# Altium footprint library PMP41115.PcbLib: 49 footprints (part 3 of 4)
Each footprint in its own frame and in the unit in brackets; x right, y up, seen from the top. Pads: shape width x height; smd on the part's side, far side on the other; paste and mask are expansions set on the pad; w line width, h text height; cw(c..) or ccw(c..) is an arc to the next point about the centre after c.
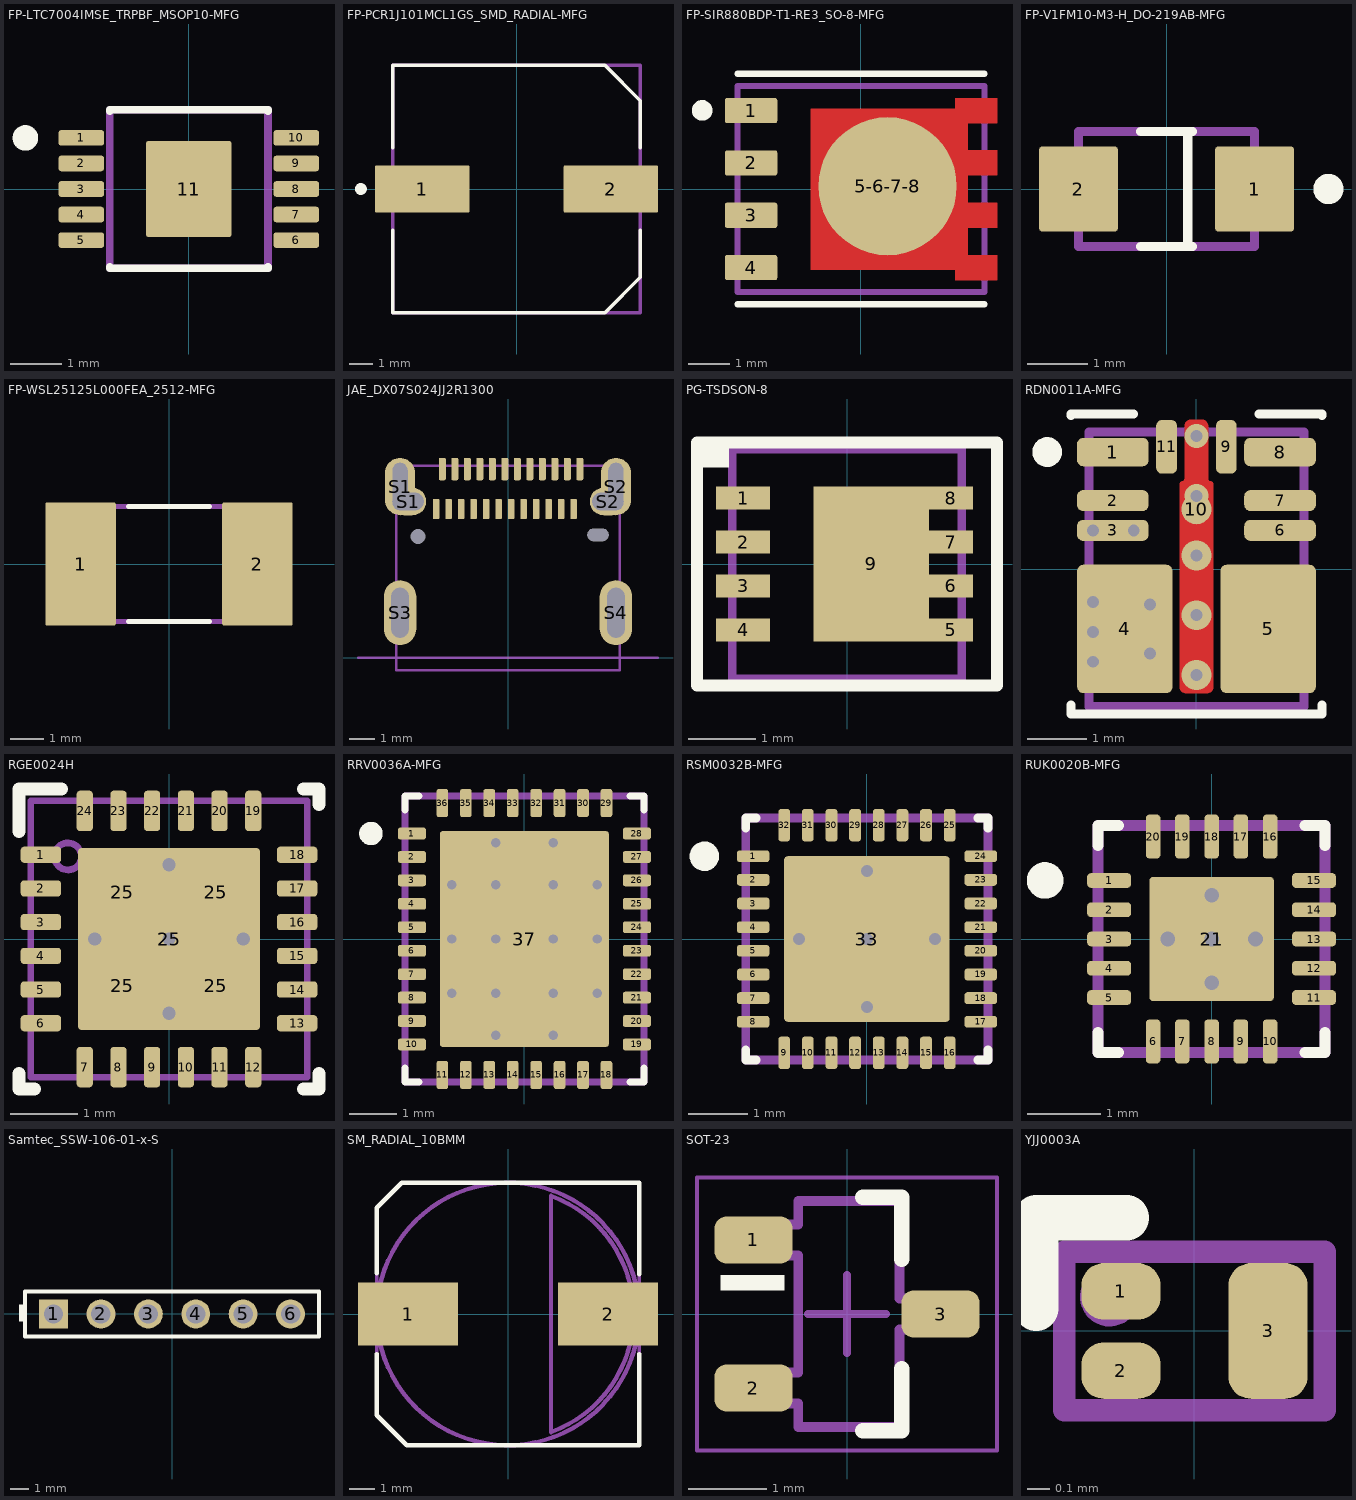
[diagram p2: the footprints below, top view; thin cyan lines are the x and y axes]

## FP-LTC7004IMSE_TRPBF_MSOP10-MFG [mm]
height 4.8
pads (11):
  rrect33% 0.889x0.305 smd paste+0 mask+0: 1(-2.105,1) 2(-2.105,0.5) 3(-2.105,0) 4(-2.105,-0.5) 5(-2.105,-1) 6(2.105,-1) 7(2.105,-0.5) 8(2.105,0) 9(2.105,0.5) 10(2.105,1)
  rrect6% 1.68x1.88 smd paste+0 mask+0: 11(0,0)
Top Overlay:
  circle w0.25: c-3.2,1 r0.125
  lines w0.15: -1.551,-1.528 -1.551,-1.551 1.551,-1.551 1.551,-1.528 ; -1.551,1.528 -1.551,1.551 1.551,1.551 1.551,1.528
Mechanical 5:
  lines w0.15: -1.551,-1.551 1.551,-1.551 1.551,1.551 -1.551,1.551 -1.551,-1.551
  text ".Designator" at 0,0 h0.5
3D body "IC_LTC7004IMSE_TRPBF_MSOP10.STEP": height 0.25, standoff 0, extent -2.65,-1.803 2.65,1.803

## FP-PCR1J101MCL1GS_SMD_RADIAL-MFG [mm]
height 4.8
pads (2):
  rrect5% 4x2 smd paste+0 mask+0: 1(-4,0) 2(4,0)
Top Overlay:
  circle w0.25: c-6.6,0 r0.125
  lines w0.15: -5.25,-1.75 -5.25,-5.25 3.75,-5.25 5.25,-3.75 5.25,-1.75 ; -5.25,1.75 -5.25,5.25 3.75,5.25 5.25,3.75 5.25,1.75
Mechanical 5:
  lines w0.15: -5.25,-5.25 5.25,-5.25 5.25,5.25 -5.25,5.25 -5.25,-5.25
  text ".Designator" at 0,0 h0.5
3D body "Cap_PCR1J101MCL1GS_SMD_RADIAL.STEP": height 0.25, standoff 0, extent -6.25,-5.5 6.25,5.5

## FP-SIR880BDP-T1-RE3_SO-8-MFG [mil]
height 188.98
pads (5):
  rrect16% 50x24 smd paste+0 mask+0: 1(-105,75) 2(-105,25) 3(-105,-25) 4(-105,-75)
  round 132.13 smd paste+0 mask+0: 5-6-7-8(25.41,2.72)
Top Layer:
  region: -48,77 90,77 90,87 130,87 130,63 102,63 102,37 130,37 130,13 102,13 102,-13 130,-13 130,-37 102,-37 102,-63 130,-63 130,-87 90,-87 90,-77 -48,-77
Top Overlay:
  circle w9.84: c-151.77,75.19 r4.92
  lines w5.91: -117.91,-110.04 117.91,-110.04 ; -117.91,110.24 117.91,110.24
Mechanical 5:
  lines w5.91: -117.91,-98.43 117.91,-98.43 117.91,98.43 -117.91,98.43 -117.91,-98.43
  text ".Designator" at 1.97,8.53 h19.68
3D body "Trans_SIR880BDP-T1-RE3_SO-8.STEP": height 46.07, standoff 0, extent -120.41,-102.22 121.72,100.53

## FP-V1FM10-M3-H_DO-219AB-MFG [mm]
height 1.1
pads (2):
  rrect8% 1.3x1.4 smd paste+0 mask+0: 1(1.45,0) 2(-1.45,0)
Top Overlay:
  circle w0.25: c2.667,0 r0.125
  lines w0.15: -0.425,-0.95 0.425,-0.95 ; -0.425,0.95 0.425,0.95 ; 0.35,-0.87 0.35,0.87
Mechanical 5:
  lines w0.15: -1.45,-0.95 -1.45,0.95 1.45,0.95 1.45,-0.95 -1.45,-0.95
  text ".Designator" at 0,0 h0.5
3D body "Diode_V1FM10-M3-H_DO-219AB.STEP": height 1.08, standoff 0, extent -1.85,-0.9 1.85,0.9

## FP-WSL25125L000FEA_2512-MFG [mm]
height 4.8
pads (2):
  rrect5% 2.11x3.68 smd paste+0 mask+0: 1(-2.645,0) 2(2.645,0)
Top Overlay:
  lines w0.15: -1.215,-1.717 1.215,-1.717 ; -1.215,1.717 1.215,1.717
Mechanical 5:
  lines w0.15: -3.302,-1.717 -3.302,1.717 3.302,1.717 3.302,-1.717 -3.302,-1.717
  text ".Designator" at 0.05,0.217 h0.5
3D body "Res_WSL25125L000FEA_2512.STEP": height 0.25, standoff 0, extent -3.8,-1.94 3.8,1.94

## JAE_DX07S024JJ2R1300 [mm] "Receptacle, USB 3.1 Type C, R/A, SMT"
height 3.29
pads (32):
  rrect37% 0.27x0.9 smd: A1(-2.625,7.55) A2(-2.125,7.55) A3(-1.625,7.55) A4(-1.125,7.55) A5(-0.625,7.55) A6(-0.125,7.55) A7(0.375,7.55) A8(0.875,7.55) A9(1.375,7.55) A10(1.875,7.55) A11(2.375,7.55) A12(2.875,7.55)
  round 0.3 hole 0.6 unplated mask+0.102: ALIGN1(-3.6,4.85)
  rrect100% 0.55x0.3 hole 0.5 slot 0.85 at 0 deg unplated mask+0.102: ALIGN2(3.6,4.915)
  rrect37% 0.27x0.8 smd: B1(2.625,5.95) B2(2.125,5.95) B3(1.625,5.95) B4(1.125,5.95) B5(0.625,5.95) B6(0.125,5.95) B7(-0.375,5.95) B8(-0.875,5.95) B9(-1.375,5.95) B10(-1.875,5.95) B11(-2.375,5.95) B12(-2.875,5.95)
  rrect100% 1.2x2.3 hole 0.6 slot 1.9 at 90 deg: S1(-4.32,6.85) S2(4.32,6.85)
  rrect100% 1.45x1.1 hole 0.7 slot 1.25 at 0 deg: S1(-3.995,6.25) S2(3.995,6.25)
  rrect100% 1.3x2.6 hole 0.7 slot 2 at 90 deg: S3(-4.32,1.8) S4(4.32,1.8)
Mechanical 1:
  lines w0.1: -6,0 6,0
Mechanical 5:
  lines w0.1: -4.47,-0.5 -4.47,7.67 -3.47,7.67 3.47,7.67 4.47,7.67 4.47,-0.5 3.47,-0.5 -3.47,-0.5 -4.47,-0.5
  text ".Designator" at -1.8,4.336 h1.02
3D body "DX07S024JJ2R1300.stp": height 3.14, standoff -0.6, extent -4.47,-0.5 4.47,7.67

## PG-TSDSON-8 [mm] "Infineon recommended land pattern"
height 1.1
pads (9):
  rect 0.8x0.34 smd: 1(-1.538,0.975) 2(-1.538,0.325) 3(-1.538,-0.325) 4(-1.538,-0.975)
  rect 0.65x0.34 smd: 5(1.538,-0.975) 6(1.538,-0.325) 7(1.538,0.325) 8(1.538,0.975)
  rect 1.71x2.29 smd: 9(0.358,0)
Top Overlay:
  rectangle: -2.212,1.425 -1.75,1.76
  lines w0.178: -2.22,-1.8 0.1,-1.8 2.22,-1.8 2.22,0 2.22,1.8 0.1,1.8 -2.22,1.8 -2.22,0 -2.22,-1.8
Mechanical 5:
  lines w0.127: -1.7,-1.7 -1.7,1.7 1.7,1.7 1.7,-1.7 -1.7,-1.7
  text ".Designator" at -1.538,-0.325 h0.76
3D body "PG-TSDSON-8.stp": height 1.1, standoff 0, extent -1.7,-1.7 1.7,1.7

## RDN0011A-MFG [mm]
pads (11):
  rrect42% 1.2x0.475 smd paste-1000 mask-1000: 1(-1.4,1.962) 8(1.4,1.962)
  rrect57% 1.2x0.35 smd paste-1000 mask-1000: 2(-1.4,1.15) 3(-1.4,0.65) 6(1.4,0.65) 7(1.4,1.15)
  rrect13% 1.6x2.15 smd paste-1000 mask-1000: 4(-1.2,-1) 5(1.2,-1)
  rrect57% 0.35x0.9 smd paste-1000 mask-1000: 9(0.5,2.05) 11(-0.5,2.05)
  round 0.504 smd paste-1000 mask-1000: 10(0,1.005)
via 0,-1.77 diameter 0.5 hole 0.2
via 0,-0.77 diameter 0.5 hole 0.2
via 0,0.23 diameter 0.5 hole 0.2
via 0,1.23 diameter 0.4 hole 0.2
via 0,2.23 diameter 0.4 hole 0.2
via -1.73,-0.55 diameter 0.5 hole 0.2
via -1.73,-1.05 diameter 0.5 hole 0.2
via -1.73,-1.55 diameter 0.5 hole 0.2
via -0.78,-0.59 diameter 0.5 hole 0.2
via -0.78,-1.41 diameter 0.5 hole 0.2
via -1.73,0.65 diameter 0.35 hole 0.2
via -1.05,0.65 diameter 0.35 hole 0.2
Top Layer:
  region: -0.2,2.4 -0.2,2.42 -0.185,2.457 -0.157,2.485 -0.12,2.5 -0.1,2.5 0.1,2.5 0.12,2.5 0.157,2.485 0.185,2.457 0.2,2.42 0.2,2.4 0.2,1.515 0.201,1.507 0.207,1.493 0.218,1.482 0.232,1.476 0.24,1.475 0.248,1.475 0.263,1.469 0.274,1.458 0.28,1.443 0.28,1.435 0.28,-1.975 0.28,-1.995 0.265,-2.032 0.237,-2.06 0.2,-2.075 0.18,-2.075 -0.18,-2.075 -0.2,-2.075 -0.237,-2.06 -0.265,-2.032 -0.28,-1.995 -0.28,-1.975 -0.28,1.435 -0.28,1.443 -0.274,1.458 -0.263,1.469 -0.248,1.475 -0.24,1.475 -0.232,1.476 -0.218,1.482 -0.207,1.493 -0.201,1.507 -0.2,1.515
Top Overlay:
  circle w0.25: c-2.5,1.962 r0.125
  lines w0.15: -2.1,-2.275 -2.1,-2.425 2.1,-2.425 2.1,-2.275 ; -2.1,2.575 -2.1,2.6 -1.05,2.6 ; 1.05,2.6 2.1,2.6 2.1,2.575
Top Paste:
  drawing of 23 lines, arcs and shapes, not listed
Top Solder:
  drawing of 11 lines, arcs and shapes, not listed
Mechanical 5:
  lines w0.15: -1.8,-2.3 -1.8,2.3 1.8,2.3 1.8,-2.3 -1.8,-2.3
  text ".Designator" at 0.05,0.317 h0.5
3D body "IC_TPSM365R6RDNR_QFN-FCMOD11.STEP": height 2.1, standoff 0, extent -1.75,-2.25 1.75,2.25

## RGE0024H [mm] "QFN, 24-Leads, Body 4x4mm, Pitch 0.5mm, Thermal Pad 2.7x2.7mm, TI Recommended"
height 1
pads (29):
  rrect42% 0.6x0.24 smd: 1(-1.9,1.25) 2(-1.9,0.75) 3(-1.9,0.25) 4(-1.9,-0.25) 5(-1.9,-0.75) 6(-1.9,-1.25) 13(1.9,-1.25) 14(1.9,-0.75) 15(1.9,-0.25) 16(1.9,0.25) 17(1.9,0.75) 18(1.9,1.25)
  rrect42% 0.24x0.6 smd: 7(-1.25,-1.9) 8(-0.75,-1.9) 9(-0.25,-1.9) 10(0.25,-1.9) 11(0.75,-1.9) 12(1.25,-1.9) 19(1.25,1.9) 20(0.75,1.9) 21(0.25,1.9) 22(-0.25,1.9) 23(-0.75,1.9) 24(-1.25,1.9)
  rrect50% 1.19x1.19 on Top Paste: 25(-0.695,-0.695) 25(-0.695,0.695) 25(0.695,-0.695) 25(0.695,0.695)
  rrect4% 2.7x2.7 smd paste-1.35: 25(0,0)
via 0,-1.1 diameter 0.5 hole 0.2
via 1.1,0 diameter 0.5 hole 0.2
via 0,0 diameter 0.5 hole 0.2
via -1.1,0 diameter 0.5 hole 0.2
via 0,1.1 diameter 0.5 hole 0.2
Top Overlay:
  lines w0.2: -2.225,-2 -2.225,-2.225 -2,-2.225 ; -2.225,1.6 -2.225,2.225 -1.6,2.225 ; 2,-2.225 2.225,-2.225 2.225,-2 ; 2,2.225 2.225,2.225 2.225,2
Mechanical 5:
  circle w0.1: c-1.5,1.225 r0.2
  lines w0.1: -2.05,-2.05 -2.05,2.05 2.05,2.05 2.05,-2.05 -2.05,-2.05
  text ".Designator" at -1.9,-0.7 h1.8
3D body: height 1, standoff 0, extent -2.075,-2.075 2.075,2.075
3D body: height 1.01, standoff 0.5, extent -1.699,1.026 -1.301,1.424

## RRV0036A-MFG [mm]
height 4.8
pads (37):
  rrect40% 0.6x0.25 smd paste+0 mask+0: 1(-2.4,2.25) 2(-2.4,1.75) 3(-2.4,1.25) 4(-2.4,0.75) 5(-2.4,0.25) 6(-2.4,-0.25) 7(-2.4,-0.75) 8(-2.4,-1.25) 9(-2.4,-1.75) 10(-2.4,-2.25) 19(2.4,-2.25) 20(2.4,-1.75) 21(2.4,-1.25) 22(2.4,-0.75) 23(2.4,-0.25) 24(2.4,0.25) 25(2.4,0.75) 26(2.4,1.25) 27(2.4,1.75) 28(2.4,2.25)
  rrect40% 0.25x0.6 smd paste+0 mask+0: 11(-1.75,-2.9) 12(-1.25,-2.9) 13(-0.75,-2.9) 14(-0.25,-2.9) 15(0.25,-2.9) 16(0.75,-2.9) 17(1.25,-2.9) 18(1.75,-2.9) 29(1.75,2.9) 30(1.25,2.9) 31(0.75,2.9) 32(0.25,2.9) 33(-0.25,2.9) 34(-0.75,2.9) 35(-1.25,2.9) 36(-1.75,2.9)
  rrect3% 3.6x4.6 smd paste-1000 mask+0: 37(0,0)
via 0.615,-2.05 diameter 0.5 hole 0.2
via -0.615,-2.05 diameter 0.5 hole 0.2
via 0.615,2.05 diameter 0.5 hole 0.2
via -0.615,2.05 diameter 0.5 hole 0.2
via 0.615,0 diameter 0.5 hole 0.2
via -0.615,0 diameter 0.5 hole 0.2
via 0.615,-1.16 diameter 0.5 hole 0.2
via -0.615,-1.16 diameter 0.5 hole 0.2
via 0.615,1.16 diameter 0.5 hole 0.2
via -0.615,1.16 diameter 0.5 hole 0.2
via 1.55,1.16 diameter 0.5 hole 0.2
via -1.55,1.16 diameter 0.5 hole 0.2
via 1.55,-1.16 diameter 0.5 hole 0.2
via -1.55,-1.16 diameter 0.5 hole 0.2
via 1.55,0 diameter 0.5 hole 0.2
via -1.55,0 diameter 0.5 hole 0.2
Top Overlay:
  circle w0.25: c-3.275,2.25 r0.125
  lines w0.15: -2.55,-2.75 -2.55,-3.05 -2.25,-3.05 ; -2.55,2.75 -2.55,3.05 -2.25,3.05 ; 2.25,-3.05 2.55,-3.05 2.55,-2.75 ; 2.25,3.05 2.55,3.05 2.55,2.75
Top Paste:
  drawing of 12 lines, arcs and shapes, not listed
Mechanical 5:
  lines w0.15: -2.55,-3.05 -2.55,3.05 2.55,3.05 2.55,-3.05 -2.55,-3.05
  text ".Designator" at 0.05,0.217 h0.5
3D body "IC_BQ25751RRVT_VQFN36.STEP": height 0.25, standoff 0, extent -2.8,-3.3 2.8,3.3

## RSM0032B-MFG [mm]
height 4.8
pads (33):
  rrect50% 0.55x0.2 smd paste+0 mask+0: 1(-1.925,1.4) 2(-1.925,1) 3(-1.925,0.6) 4(-1.925,0.2) 5(-1.925,-0.2) 6(-1.925,-0.6) 7(-1.925,-1) 8(-1.925,-1.4) 17(1.925,-1.4) 18(1.925,-1) 19(1.925,-0.6) 20(1.925,-0.2) 21(1.925,0.2) 22(1.925,0.6) 23(1.925,1) 24(1.925,1.4)
  rrect50% 0.2x0.55 smd paste+0 mask+0: 9(-1.4,-1.925) 10(-1,-1.925) 11(-0.6,-1.925) 12(-0.2,-1.925) 13(0.2,-1.925) 14(0.6,-1.925) 15(1,-1.925) 16(1.4,-1.925) 25(1.4,1.925) 26(1,1.925) 27(0.6,1.925) 28(0.2,1.925) 29(-0.2,1.925) 30(-0.6,1.925) 31(-1,1.925) 32(-1.4,1.925)
  rrect4% 2.8x2.8 smd paste-1000 mask+0: 33(0,0)
via 0,-1.15 diameter 0.5 hole 0.2
via 0,1.15 diameter 0.5 hole 0.2
via 1.15,0 diameter 0.5 hole 0.2
via 0,0 diameter 0.5 hole 0.2
via -1.15,0 diameter 0.5 hole 0.2
Top Overlay:
  circle w0.25: c-2.75,1.4 r0.125
  lines w0.15: -2.05,-1.875 -2.05,-2.05 -1.875,-2.05 ; -2.05,1.875 -2.05,2.05 -1.875,2.05 ; 1.875,-2.05 2.05,-2.05 2.05,-1.875 ; 1.875,2.05 2.05,2.05 2.05,1.875
Top Paste:
  region: 1.33,-0.15 1.33,-1.28 1.33,-1.29 1.322,-1.308 1.308,-1.322 1.29,-1.33 1.28,-1.33 0.15,-1.33 0.14,-1.33 0.122,-1.322 0.108,-1.308 0.1,-1.29 0.1,-1.28 0.1,-0.15 0.1,-0.14 0.108,-0.122 0.122,-0.108 0.14,-0.1 0.15,-0.1 1.28,-0.1 1.29,-0.1 1.308,-0.108 1.322,-0.122 1.33,-0.14
  region: -1.28,-1.33 -1.29,-1.33 -1.308,-1.322 -1.322,-1.308 -1.33,-1.29 -1.33,-1.28 -1.33,-0.15 -1.33,-0.14 -1.322,-0.122 -1.308,-0.108 -1.29,-0.1 -1.28,-0.1 -0.15,-0.1 -0.14,-0.1 -0.122,-0.108 -0.108,-0.122 -0.1,-0.14 -0.1,-0.15 -0.1,-1.28 -0.1,-1.29 -0.108,-1.308 -0.122,-1.322 -0.14,-1.33 -0.15,-1.33
  region: 0.1,0.15 0.1,1.28 0.1,1.29 0.108,1.308 0.122,1.322 0.14,1.33 0.15,1.33 1.28,1.33 1.29,1.33 1.308,1.322 1.322,1.308 1.33,1.29 1.33,1.28 1.33,0.15 1.33,0.14 1.322,0.122 1.308,0.108 1.29,0.1 1.28,0.1 0.15,0.1 0.14,0.1 0.122,0.108 0.108,0.122 0.1,0.14
  region: -0.1,0.15 -0.1,0.14 -0.108,0.122 -0.122,0.108 -0.14,0.1 -0.15,0.1 -1.28,0.1 -1.29,0.1 -1.308,0.108 -1.322,0.122 -1.33,0.14 -1.33,0.15 -1.33,1.28 -1.33,1.29 -1.322,1.308 -1.308,1.322 -1.29,1.33 -1.28,1.33 -0.15,1.33 -0.14,1.33 -0.122,1.322 -0.108,1.308 -0.1,1.29 -0.1,1.28
Mechanical 5:
  lines w0.15: -2.05,-2.05 -2.05,2.05 2.05,2.05 2.05,-2.05 -2.05,-2.05
  text ".Designator" at 0.05,0.217 h0.5
3D body "IC_TPS26750RSMR_VQFN32.STEP": height 0.25, standoff 0, extent -2.3,-2.3 2.3,2.3

## RUK0020B-MFG [mm]
height 4.8
pads (21):
  rrect50% 0.6x0.2 smd paste+0 mask+0: 1(-1.4,0.8) 2(-1.4,0.4) 3(-1.4,0) 4(-1.4,-0.4) 5(-1.4,-0.8) 11(1.4,-0.8) 12(1.4,-0.4) 13(1.4,0) 14(1.4,0.4) 15(1.4,0.8)
  rrect50% 0.2x0.6 smd paste+0 mask+0: 6(-0.8,-1.4) 7(-0.4,-1.4) 8(0,-1.4) 9(0.4,-1.4) 10(0.8,-1.4) 16(0.8,1.4) 17(0.4,1.4) 18(0,1.4) 19(-0.4,1.4) 20(-0.8,1.4)
  rrect6% 1.7x1.7 smd paste-1000 mask+0: 21(0,0)
via 0,0.6 diameter 0.5 hole 0.2
via 0,-0.6 diameter 0.5 hole 0.2
via 0.6,0 diameter 0.5 hole 0.2
via 0,0 diameter 0.5 hole 0.2
via -0.6,0 diameter 0.5 hole 0.2
Top Overlay:
  circle w0.25: c-2.275,0.8 r0.125
  lines w0.15: -1.55,-1.275 -1.55,-1.55 -1.275,-1.55 ; -1.55,1.275 -1.55,1.55 -1.275,1.55 ; 1.275,-1.55 1.55,-1.55 1.55,-1.275 ; 1.275,1.55 1.55,1.55 1.55,1.275
Top Paste:
  region: 0.095,-0.145 0.095,-0.135 0.103,-0.117 0.117,-0.103 0.135,-0.095 0.145,-0.095 0.795,-0.095 0.805,-0.095 0.823,-0.103 0.837,-0.117 0.845,-0.135 0.845,-0.145 0.845,-0.795 0.845,-0.805 0.837,-0.823 0.823,-0.837 0.805,-0.845 0.795,-0.845 0.145,-0.845 0.135,-0.845 0.117,-0.837 0.103,-0.823 0.095,-0.805 0.095,-0.795
  region: -0.795,-0.845 -0.805,-0.845 -0.823,-0.837 -0.837,-0.823 -0.845,-0.805 -0.845,-0.795 -0.845,-0.145 -0.845,-0.135 -0.837,-0.117 -0.823,-0.103 -0.805,-0.095 -0.795,-0.095 -0.145,-0.095 -0.135,-0.095 -0.117,-0.103 -0.103,-0.117 -0.095,-0.135 -0.095,-0.145 -0.095,-0.795 -0.095,-0.805 -0.103,-0.823 -0.117,-0.837 -0.135,-0.845 -0.145,-0.845
  region: 0.095,0.795 0.095,0.805 0.103,0.823 0.117,0.837 0.135,0.845 0.145,0.845 0.795,0.845 0.805,0.845 0.823,0.837 0.837,0.823 0.845,0.805 0.845,0.795 0.845,0.145 0.845,0.135 0.837,0.117 0.823,0.103 0.805,0.095 0.795,0.095 0.145,0.095 0.135,0.095 0.117,0.103 0.103,0.117 0.095,0.135 0.095,0.145
  region: -0.145,0.845 -0.135,0.845 -0.117,0.837 -0.103,0.823 -0.095,0.805 -0.095,0.795 -0.095,0.145 -0.095,0.135 -0.103,0.117 -0.117,0.103 -0.135,0.095 -0.145,0.095 -0.795,0.095 -0.805,0.095 -0.823,0.103 -0.837,0.117 -0.845,0.135 -0.845,0.145 -0.845,0.795 -0.845,0.805 -0.837,0.823 -0.823,0.837 -0.805,0.845 -0.795,0.845
Mechanical 5:
  lines w0.15: -1.55,-1.55 -1.55,1.55 1.55,1.55 1.55,-1.55 -1.55,-1.55
  text ".Designator" at 0,0 h0.5
3D body "IC_TPD4S480RUKR_WQFN20.STEP": height 0.25, standoff 0, extent -1.8,-1.8 1.8,1.8

## Samtec_SSW-106-01-x-S [mm] "Receptacle, 6x1, 2.54mm, TH"
height 8.64
pads (6):
  rect 1.55x1.55 hole 1.04: 1(-6.35,0)
  round 1.55 hole 1.04: 2(-3.81,0) 3(-1.27,0) 4(1.27,0) 5(3.81,0) 6(6.35,0)
Top Overlay:
  rectangle: -8.2,-0.4 -7.9,0.5
  lines w0.2: -7.874,-1.207 7.874,-1.207 7.874,1.206 -7.874,1.206 -7.874,-1.207
Mechanical 5:
  lines w0.1: -7.874,-1.207 -7.874,1.206 7.874,1.206 7.874,-1.207 -7.874,-1.207
  text ".Designator" at -1.524,-0.508 h1.02
3D body "SSW-106-01-T-S.stp": height 8.51, standoff -2.64, extent -7.874,-1.207 7.874,1.207

## SM_RADIAL_10BMM [mm] "Nichicon 10x10"
height 10.5
pads (2):
  rect 4x2.5 smd: 1(-4,0) 2(4,0)
Top Overlay:
  lines w0.178: -5.25,-1.6 -5.25,-4.046 -4.046,-5.25 5.25,-5.25 5.25,-1.6 ; -5.25,1.624 -5.25,4.25 -4.25,5.25 5.25,5.25 5.25,1.597
Mechanical 5:
  lines w0.127: -5.25,-4.046 -5.25,4.25 -4.25,5.25 5.25,5.25 5.25,-5.25 -4.046,-5.25 -5.25,-4.046
  text ".Designator" at -1.524,-0.508 h1.02
Mechanical 13:
  circle w0.178: c0,0 r5.25
  lines w0.178: 1.72,-4.725 ccw(c0,0) 1.72,4.725 1.72,-4.725
3D body: height 1, standoff 0, extent -5.251,-5.251 5.251,5.251
3D body: height 10.5, standoff 10.4, extent 1.719,-4.725 5.028,4.725
3D body: height 10.5, standoff 1, extent -5.249,-5.249 5.249,5.249

## SOT-23 [mm] "SOT23, 3-Leads, Body 2.9x1.3mm, Pitch 0.95mm, Lead Span 2.5mm, IPC Medium Density"
height 1.1
pads (3):
  rrect50% 1x0.6 smd: 1(-1.2,0.95) 2(-1.2,-0.95) 3(1.2,0)
Top Overlay:
  rectangle: -1.625,0.3 -0.8,0.5
  lines w0.2: 0.2,-1.5 0.7,-1.5 0.7,-0.7 ; 0.2,1.5 0.7,1.5 0.7,0.7
Mechanical 5:
  lines w0.127: -1.16,-1.15 -0.625,-1.15 -0.625,-1.45 0.675,-1.45 0.675,-0.2 1.21,-0.2 1.21,0.2 0.675,0.2 0.675,1.45 -0.625,1.45 -0.625,1.15 -1.16,1.15 -1.16,0.75 -0.625,0.75 -0.625,-0.75 -1.16,-0.75 -1.16,-1.15
  text ".Designator" at -0.175,1.225 h0.64
Mechanical 15:
  lines w0.05: -1.925,-1.75 -1.925,1.75 1.925,1.75 1.925,-1.75 -1.925,-1.75
  lines w0.1: -0.5,0 0.5,0 ; 0,-0.5 0,0.5
3D body "SW3dPS-sot-3p290x130ll237h100.STEP": height 1, standoff 0, extent -1.16,-1.45 1.21,1.45

## YJJ0003A [mm] "SMD, 3-Leads, Body 1x0.6mm"
height 0.22
pads (3):
  rrect80% 0.35x0.25 smd mask-0.05: 1(-0.325,0.175) 2(-0.325,-0.175)
  rrect57% 0.35x0.6 smd mask-0.05: 3(0.325,0)
Top Overlay:
  lines w0.2: -0.7,0.1 -0.7,0.5 -0.3,0.5
Mechanical 5:
  circle w0.1: c-0.375,0.15 r0.08
  lines w0.1: -0.575,-0.35 -0.575,0.35 0.575,0.35 0.575,-0.35 -0.575,-0.35
  text ".Designator'" at -0.4,-0.275 h0.45
3D body: height 0.22, standoff 0.22, extent -0.299,0.001 -0.101,0.199
3D body "YJJ0003A.stp": height 0.22, standoff 0, extent -0.5,-0.3 0.5,0.3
